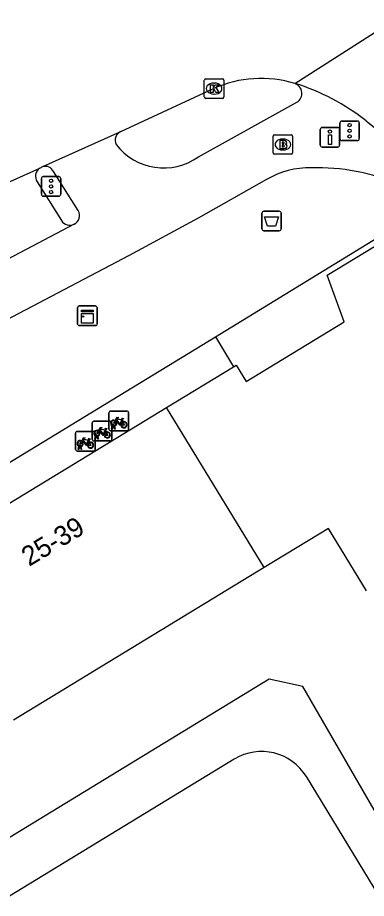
# Model space of a CAD drawing. Extents: x 159888 to 160757, y 384031 to 384746.
# Drawn here: x 160248.39 to 160266.23, y 384650.52 to 384695.58 of the extents above; entities that cross this region are included whole.
import ezdxf

# ---------------------------------------------------------------- set-up
doc = ezdxf.new("R2010")
doc.units = 0
for name, color, linetype in [('IMGEO_Afvalbak', 7, 'Continuous'), ('IMGEO_Brandkraan', 7, 'Continuous'), ('IMGEO_Drukknoppaal', 7, 'Continuous'), ('IMGEO_Fietsenrek', 7, 'Continuous'), ('IMGEO_Fietspad_open', 7, 'Continuous'), ('IMGEO_Kast', 7, 'Continuous'), ('IMGEO_Kolk', 7, 'Continuous'), ('IMGEO_Pand', 7, 'Continuous'), ('IMGEO_Pand_nummerreeks', 7, 'Continuous'), ('IMGEO_Rijbaan_lokaal_gesloten', 7, 'Continuous'), ('IMGEO_Rijbaan_regionaal_gesloten', 7, 'Continuous'), ('IMGEO_Verkeersregelinstallatiepaal', 7, 'Continuous'), ('IMGEO_Voetpad_gesloten', 7, 'Continuous'), ('IMGEO_Voetpad_open', 7, 'Continuous')]:
    doc.layers.add(name, color=color, linetype=linetype)

msp = doc.modelspace()

# ---------------------------------------------------------------- linework, layer by layer
at = {"layer": 'IMGEO_Afvalbak'}
for p, q in [((160260.984, 384685.673), (160261.774, 384685.673)), ((160261.774, 384685.673), (160260.984, 384685.673)), ((160260.884, 384684.773), (160260.884, 384685.573)), ((160260.884, 384685.573), (160260.884, 384684.773)), ((160261.874, 384685.573), (160261.874, 384684.773)), ((160261.874, 384684.773), (160261.874, 384685.573)), ((160261.774, 384684.673), (160260.984, 384684.673)), ((160260.984, 384684.673), (160261.774, 384684.673))]:
    msp.add_line(p, q, dxfattribs=at)
msp.add_lwpolyline([(160261.027, 384685.387), (160261.731, 384685.387), (160261.582, 384684.917), (160261.176, 384684.917), (160261.027, 384685.387)], dxfattribs=at)
for centre, start, end in [((160260.984, 384685.573), 90, 180), ((160260.984, 384685.573), 90, 180), ((160261.774, 384685.573), 0, 90), ((160261.774, 384685.573), 360, 90), ((160260.984, 384684.773), 180, 270), ((160260.984, 384684.773), 180, 270), ((160261.774, 384684.773), 270, 0), ((160261.774, 384684.773), 270, 0)]:
    msp.add_arc(centre, 0.1, start, end, dxfattribs=at)
at = {"layer": 'IMGEO_Brandkraan'}
for p, q in [((160261.457, 384688.661), (160261.457, 384689.513)), ((160261.532, 384689.587), (160262.384, 384689.587)), ((160261.945, 384689.367), (160261.97, 384689.367)), ((160262.458, 384689.513), (160262.458, 384688.661)), ((160261.968, 384688.807), (160261.943, 384688.807)), ((160262.384, 384688.587), (160261.532, 384688.587))]:
    msp.add_line(p, q, dxfattribs=at)
for points in [[(160261.457, 384688.661), (160261.457, 384689.513)], [(160261.532, 384689.587), (160262.384, 384689.587)], [(160261.805, 384689.287), (160261.805, 384688.887), (160262.018, 384688.887)], [(160262.036, 384689.287), (160261.805, 384689.287)], [(160262.458, 384689.513), (160262.458, 384688.661)], [(160261.984, 384689.206), (160261.93, 384689.206), (160261.93, 384689.13)], [(160261.93, 384689.13), (160261.983, 384689.13)], [(160261.992, 384689.054), (160261.93, 384689.054), (160261.93, 384688.973)], [(160261.93, 384688.973), (160261.992, 384688.973)], [(160262.384, 384688.587), (160261.532, 384688.587)]]:
    msp.add_lwpolyline(points, dxfattribs=at)
for centre, radius, start, end in [((160261.534, 384689.511), 0.0765, 91.552, 178.448), ((160261.534, 384689.511), 0.0765, 91.552, 178.448), ((160262.04, 384689.142), 0.145, 59.4692, 91.5367), ((160262.065, 384689.189), 0.0922, 285.5137, 58.1501), ((160262.382, 384689.511), 0.0765, 1.552, 88.448), ((160262.382, 384689.511), 0.0765, 1.552, 88.448), ((160261.985, 384689.168), 0.0379, 267.8285, 90.9355), ((160261.993, 384689.013), 0.0404, 269.8759, 90.5077), ((160262.024, 384689.138), 0.251, 268.6676, 293.5347), ((160262.07, 384688.997), 0.105, 301.3115, 78.989), ((160261.534, 384688.663), 0.0765, 181.552, 268.448), ((160261.534, 384688.663), 0.0765, 181.552, 268.448), ((160262.382, 384688.663), 0.0765, 271.552, 358.448), ((160262.382, 384688.663), 0.0765, 271.552, 358.448)]:
    msp.add_arc(centre, radius, start, end, dxfattribs=at)
for centre, major_axis, ratio, start_param, end_param in [((160261.944, 384689.087), (-0.387, 0.002), 0.722429, 4.712389, 7.853982), ((160261.969, 384689.087), (-0.39, 0.002), 0.717154, 1.570796, 4.712389)]:
    msp.add_ellipse(centre, major_axis=major_axis, ratio=ratio, start_param=start_param, end_param=end_param, dxfattribs=at)
at = {"layer": 'IMGEO_Drukknoppaal'}
for p, q in [((160263.872, 384689.059), (160263.872, 384689.859)), ((160263.872, 384689.859), (160263.872, 384689.059)), ((160263.972, 384689.959), (160264.762, 384689.959)), ((160264.762, 384689.959), (160263.972, 384689.959)), ((160264.862, 384689.859), (160264.862, 384689.059)), ((160264.862, 384689.059), (160264.862, 384689.859)), ((160264.762, 384688.959), (160263.972, 384688.959)), ((160263.972, 384688.959), (160264.762, 384688.959))]:
    msp.add_line(p, q, dxfattribs=at)
msp.add_lwpolyline([(160264.442, 384689.584), (160264.442, 384689.084), (160264.292, 384689.084), (160264.292, 384689.584), (160264.442, 384689.584)], dxfattribs=at)
msp.add_circle((160264.367, 384689.749), 0.085, dxfattribs=at)
for centre, start, end in [((160263.972, 384689.859), 90, 180), ((160263.972, 384689.859), 90, 180), ((160264.762, 384689.859), 0, 90), ((160264.762, 384689.859), 360, 90), ((160263.972, 384689.059), 180, 270), ((160263.972, 384689.059), 180, 270), ((160264.762, 384689.059), 270, 0), ((160264.762, 384689.059), 270, 0)]:
    msp.add_arc(centre, 0.1, start, end, dxfattribs=at)
at = {"layer": 'IMGEO_Fietsenrek'}
for p, q in [((160253.066, 384674.521), (160253.066, 384675.362)), ((160253.066, 384675.362), (160253.066, 384674.521)), ((160253.141, 384675.446), (160253.982, 384675.446)), ((160253.982, 384675.446), (160253.141, 384675.446)), ((160254.066, 384675.371), (160254.066, 384674.53)), ((160254.066, 384674.53), (160254.066, 384675.371)), ((160252.212, 384674), (160252.212, 384674.841)), ((160252.212, 384674.841), (160252.212, 384674)), ((160252.287, 384674.925), (160253.128, 384674.925)), ((160253.128, 384674.925), (160252.287, 384674.925)), ((160253.212, 384674.85), (160253.212, 384674.009)), ((160253.212, 384674.009), (160253.212, 384674.85)), ((160253.753, 384674.995), (160253.789, 384674.9)), ((160251.432, 384674.404), (160252.273, 384674.404)), ((160252.273, 384674.404), (160251.432, 384674.404)), ((160252.899, 384674.474), (160252.935, 384674.379)), ((160253.991, 384674.446), (160253.15, 384674.446)), ((160253.15, 384674.446), (160253.991, 384674.446)), ((160253.193, 384674.53), (160253.232, 384674.69)), ((160253.227, 384674.53), (160253.193, 384674.53)), ((160253.262, 384674.678), (160253.227, 384674.53)), ((160253.304, 384674.702), (160253.303, 384674.706)), ((160253.345, 384674.53), (160253.311, 384674.672)), ((160253.335, 384674.713), (160253.336, 384674.706)), ((160253.343, 384674.676), (160253.378, 384674.53)), ((160253.378, 384674.53), (160253.345, 384674.53)), ((160251.357, 384673.479), (160251.357, 384674.32)), ((160251.357, 384674.32), (160251.357, 384673.479)), ((160252.044, 384673.953), (160252.08, 384673.858)), ((160253.137, 384673.925), (160252.296, 384673.925)), ((160252.296, 384673.925), (160253.137, 384673.925)), ((160252.339, 384674.009), (160252.378, 384674.169)), ((160252.373, 384674.009), (160252.339, 384674.009)), ((160252.357, 384674.329), (160252.357, 384673.488)), ((160252.357, 384673.488), (160252.357, 384674.329)), ((160252.408, 384674.157), (160252.373, 384674.009)), ((160252.45, 384674.181), (160252.449, 384674.185)), ((160252.491, 384674.009), (160252.457, 384674.151)), ((160252.481, 384674.192), (160252.482, 384674.185)), ((160252.489, 384674.155), (160252.524, 384674.009)), ((160252.524, 384674.009), (160252.491, 384674.009)), ((160251.484, 384673.488), (160251.523, 384673.648)), ((160251.518, 384673.488), (160251.484, 384673.488)), ((160251.553, 384673.636), (160251.518, 384673.488)), ((160251.595, 384673.66), (160251.594, 384673.664)), ((160251.636, 384673.488), (160251.602, 384673.63)), ((160251.626, 384673.671), (160251.627, 384673.664)), ((160251.634, 384673.634), (160251.669, 384673.488)), ((160251.669, 384673.488), (160251.636, 384673.488)), ((160252.282, 384673.404), (160251.441, 384673.404)), ((160251.441, 384673.404), (160252.282, 384673.404))]:
    msp.add_line(p, q, dxfattribs=at)
for points in [[(160253.4, 384674.92), (160253.348, 384674.83), (160253.308, 384674.805), (160253.309, 384674.852), (160253.364, 384674.946)], [(160253.379, 384674.972), (160253.474, 384675.136), (160253.56, 384675.122), (160253.562, 384675.113), (160253.506, 384675.102), (160253.479, 384675.057), (160253.735, 384675.016)], [(160253.675, 384674.728), (160253.625, 384674.728), (160253.434, 384674.979), (160253.415, 384674.947)], [(160253.722, 384674.991), (160253.465, 384675.032), (160253.448, 384675.003), (160253.615, 384674.783), (160253.722, 384674.991)], [(160253.77, 384674.893), (160253.74, 384674.97), (160253.631, 384674.752), (160253.674, 384674.752)], [(160253.704, 384674.752), (160253.824, 384674.751), (160253.78, 384674.865)], [(160253.8, 384674.872), (160253.855, 384674.727), (160253.705, 384674.727)], [(160253.735, 384675.016), (160253.76, 384675.065), (160253.754, 384675.069), (160253.731, 384675.073), (160253.719, 384675.08), (160253.718, 384675.083), (160253.72, 384675.088), (160253.815, 384675.073), (160253.817, 384675.063), (160253.807, 384675.05), (160253.795, 384675.044), (160253.781, 384675.05), (160253.753, 384674.995)], [(160252.546, 384674.399), (160252.494, 384674.309), (160252.454, 384674.284), (160252.455, 384674.331), (160252.51, 384674.425)], [(160252.525, 384674.451), (160252.62, 384674.615), (160252.706, 384674.601), (160252.708, 384674.592), (160252.652, 384674.581), (160252.625, 384674.536), (160252.881, 384674.495)], [(160252.821, 384674.207), (160252.771, 384674.207), (160252.58, 384674.458), (160252.561, 384674.426)], [(160252.868, 384674.47), (160252.611, 384674.511), (160252.594, 384674.482), (160252.761, 384674.262), (160252.868, 384674.47)], [(160252.916, 384674.372), (160252.886, 384674.449), (160252.777, 384674.231), (160252.82, 384674.231)], [(160252.881, 384674.495), (160252.906, 384674.544), (160252.9, 384674.548), (160252.877, 384674.552), (160252.865, 384674.559), (160252.864, 384674.562), (160252.866, 384674.567), (160252.961, 384674.552), (160252.963, 384674.542), (160252.953, 384674.529), (160252.941, 384674.523), (160252.927, 384674.529), (160252.899, 384674.474)], [(160251.67, 384673.93), (160251.765, 384674.094), (160251.851, 384674.08), (160251.853, 384674.071), (160251.797, 384674.06), (160251.77, 384674.015), (160252.026, 384673.974)], [(160251.966, 384673.686), (160251.916, 384673.686), (160251.725, 384673.937), (160251.706, 384673.905)], [(160252.013, 384673.949), (160251.756, 384673.99), (160251.739, 384673.961), (160251.906, 384673.741), (160252.013, 384673.949)], [(160252.061, 384673.851), (160252.031, 384673.928), (160251.922, 384673.71), (160251.965, 384673.71)], [(160252.026, 384673.974), (160252.051, 384674.023), (160252.045, 384674.027), (160252.022, 384674.031), (160252.01, 384674.038), (160252.009, 384674.041), (160252.011, 384674.046), (160252.106, 384674.031), (160252.108, 384674.021), (160252.098, 384674.008), (160252.086, 384674.002), (160252.072, 384674.008), (160252.044, 384673.953)], [(160252.85, 384674.231), (160252.97, 384674.23), (160252.926, 384674.344)], [(160252.946, 384674.351), (160253.001, 384674.206), (160252.851, 384674.206)], [(160251.691, 384673.878), (160251.639, 384673.788), (160251.599, 384673.763), (160251.6, 384673.81), (160251.655, 384673.904)], [(160251.995, 384673.71), (160252.115, 384673.709), (160252.071, 384673.823)], [(160252.091, 384673.83), (160252.146, 384673.685), (160251.996, 384673.685)]]:
    msp.add_lwpolyline(points, dxfattribs=at)
for centre, radius, start, end in [((160253.144, 384675.368), 0.0779, 92.4484, 184.2845), ((160253.144, 384675.368), 0.0779, 92.4484, 184.2845), ((160253.988, 384675.368), 0.0779, 2.4484, 94.2845), ((160253.988, 384675.368), 0.0779, 2.4484, 94.2845), ((160252.29, 384674.847), 0.0779, 92.4484, 184.2845), ((160252.29, 384674.847), 0.0779, 92.4484, 184.2845), ((160253.134, 384674.847), 0.0779, 2.4484, 94.2845), ((160253.134, 384674.847), 0.0779, 2.4484, 94.2845), ((160253.306, 384674.831), 0.159, 62.6766, 242.1369), ((160253.306, 384674.831), 0.129, 63.3192, 238.903), ((160253.306, 384674.831), 0.129, 283.6043, 43.4302), ((160253.306, 384674.831), 0.159, 283.5766, 46.6042), ((160253.833, 384674.747), 0.159, 113.3408, 178.3217), ((160253.833, 384674.747), 0.159, 187.0065, 105.7708), ((160253.833, 384674.747), 0.129, 113.923, 177.9556), ((160253.833, 384674.747), 0.129, 188.6715, 104.5883), ((160251.435, 384674.326), 0.0779, 92.4484, 184.2845), ((160251.435, 384674.326), 0.0779, 92.4484, 184.2845), ((160252.279, 384674.326), 0.0779, 2.4484, 94.2845), ((160252.279, 384674.326), 0.0779, 2.4484, 94.2845), ((160252.452, 384674.31), 0.159, 62.6766, 242.1369), ((160252.452, 384674.31), 0.129, 63.3192, 238.903), ((160252.452, 384674.31), 0.129, 283.6043, 43.4302), ((160252.452, 384674.31), 0.159, 283.5766, 46.6042), ((160252.979, 384674.226), 0.159, 113.3408, 178.3217), ((160252.979, 384674.226), 0.159, 187.0065, 105.7708), ((160253.144, 384674.524), 0.0779, 182.4484, 274.2845), ((160253.144, 384674.524), 0.0779, 182.4484, 274.2845), ((160253.286, 384674.702), 0.0499, 12.8025, 158.6934), ((160253.306, 384674.831), 0.159, 253.9967, 271.7867), ((160253.286, 384674.702), 0.0174, 12.8025, 163.4502), ((160253.306, 384674.831), 0.129, 253.415, 269.0204), ((160253.988, 384674.524), 0.0779, 272.4484, 4.2845), ((160253.988, 384674.524), 0.0779, 272.4484, 4.2845), ((160251.597, 384673.789), 0.159, 62.6766, 242.1369), ((160251.597, 384673.789), 0.129, 63.3192, 238.903), ((160252.29, 384674.003), 0.0779, 182.4484, 274.2845), ((160252.29, 384674.003), 0.0779, 182.4484, 274.2845), ((160252.432, 384674.181), 0.0499, 12.8025, 158.6934), ((160252.452, 384674.31), 0.159, 253.9967, 271.7867), ((160252.432, 384674.181), 0.0174, 12.8025, 163.4502), ((160252.452, 384674.31), 0.129, 253.415, 269.0204), ((160252.979, 384674.226), 0.129, 113.923, 177.9556), ((160252.979, 384674.226), 0.129, 188.6715, 104.5883), ((160253.134, 384674.003), 0.0779, 272.4484, 4.2845), ((160253.134, 384674.003), 0.0779, 272.4484, 4.2845), ((160251.435, 384673.482), 0.0779, 182.4484, 274.2845), ((160251.435, 384673.482), 0.0779, 182.4484, 274.2845), ((160251.577, 384673.66), 0.0499, 12.8025, 158.6934), ((160251.597, 384673.789), 0.159, 253.9967, 271.7867), ((160251.577, 384673.66), 0.0174, 12.8025, 163.4502), ((160251.597, 384673.789), 0.129, 253.415, 269.0204), ((160251.597, 384673.789), 0.129, 283.6043, 43.4302), ((160251.597, 384673.789), 0.159, 283.5766, 46.6042), ((160252.124, 384673.705), 0.159, 113.3408, 178.3217), ((160252.124, 384673.705), 0.159, 187.0065, 105.7708), ((160252.124, 384673.705), 0.129, 113.923, 177.9556), ((160252.124, 384673.705), 0.129, 188.6715, 104.5883), ((160252.279, 384673.482), 0.0779, 272.4484, 4.2845), ((160252.279, 384673.482), 0.0779, 272.4484, 4.2845)]:
    msp.add_arc(centre, radius, start, end, dxfattribs=at)
at = {"layer": 'IMGEO_Fietspad_open'}
for points in [[(160257.644, 384688.461), (160262.672, 384691.247)], [(160251.497, 384685.709), (160250.227, 384687.713)], [(160261.124, 384687.295), (160257.631, 384685.322), (160254.104, 384683.407), (160243.453, 384677.816), (160234.319, 384673.277)], [(160251.28, 384685.007), (160246.943, 384682.725)]]:
    msp.add_lwpolyline(points, dxfattribs=at)
for centre, radius, start, end in [((160262.401, 384691.706), 0.533, 300.5782, 71.3841), ((160253.884, 384689.3), 0.5, 114.6774, 204.3436), ((160255.862, 384690.947), 3.059, 217.2863, 305.6363), ((160249.801, 384687.489), 0.481, 27.7801, 103.348), ((160263.277, 384683.719), 4.174, 88.0959, 121.0563), ((160263.758, 384677.463), 10.433, 66.5927, 91.8798), ((160251.064, 384685.458), 0.501, 295.6158, 30.0297)]:
    msp.add_arc(centre, radius, start, end, dxfattribs=at)
at = {"layer": 'IMGEO_Kast'}
for p, q in [((160251.461, 384679.901), (160251.461, 384680.742)), ((160251.461, 384680.742), (160251.461, 384679.901)), ((160251.536, 384680.826), (160252.377, 384680.826)), ((160252.377, 384680.826), (160251.536, 384680.826)), ((160252.461, 384680.751), (160252.461, 384679.91)), ((160252.461, 384679.91), (160252.461, 384680.751)), ((160252.386, 384679.826), (160251.545, 384679.826)), ((160251.545, 384679.826), (160252.386, 384679.826))]:
    msp.add_line(p, q, dxfattribs=at)
for points in [[(160251.656, 384680.616), (160252.256, 384680.616), (160252.256, 384680.531), (160251.656, 384680.531), (160251.656, 384680.616)], [(160251.656, 384680.441), (160252.256, 384680.441), (160252.256, 384679.952), (160251.656, 384679.952), (160251.656, 384680.441)]]:
    msp.add_lwpolyline(points, dxfattribs=at)
msp.add_circle((160251.74, 384680.29), 0.0377, dxfattribs=at)
for centre, start, end in [((160251.539, 384680.748), 92.4484, 184.2845), ((160251.539, 384680.748), 92.4484, 184.2845), ((160252.383, 384680.748), 2.4484, 94.2845), ((160252.383, 384680.748), 2.4484, 94.2845), ((160251.539, 384679.904), 182.4484, 274.2845), ((160251.539, 384679.904), 182.4484, 274.2845), ((160252.383, 384679.904), 272.4484, 4.2845), ((160252.383, 384679.904), 272.4484, 4.2845)]:
    msp.add_arc(centre, 0.0779, start, end, dxfattribs=at)
at = {"layer": 'IMGEO_Kolk'}
for p, q in [((160258.017, 384692.448), (160258.869, 384692.448)), ((160257.942, 384691.522), (160257.942, 384692.374)), ((160258.43, 384692.228), (160258.455, 384692.228)), ((160258.943, 384692.374), (160258.943, 384691.522)), ((160258.453, 384691.668), (160258.428, 384691.668)), ((160258.869, 384691.448), (160258.017, 384691.448))]:
    msp.add_line(p, q, dxfattribs=at)
for points in [[(160258.017, 384692.448), (160258.869, 384692.448)], [(160257.942, 384691.522), (160257.942, 384692.374)], [(160258.263, 384692.148), (160258.386, 384692.148), (160258.386, 384691.997), (160258.516, 384692.148), (160258.68, 384692.148), (160258.534, 384691.997), (160258.687, 384691.748), (160258.535, 384691.748), (160258.45, 384691.912), (160258.386, 384691.845), (160258.386, 384691.748), (160258.263, 384691.748), (160258.263, 384692.148)], [(160258.943, 384692.374), (160258.943, 384691.522)], [(160258.869, 384691.448), (160258.017, 384691.448)]]:
    msp.add_lwpolyline(points, dxfattribs=at)
for centre, start, end in [((160258.019, 384692.372), 91.552, 178.448), ((160258.019, 384692.372), 91.552, 178.448), ((160258.867, 384692.372), 1.552, 88.448), ((160258.867, 384692.372), 1.552, 88.448), ((160258.019, 384691.524), 181.552, 268.448), ((160258.019, 384691.524), 181.552, 268.448), ((160258.867, 384691.524), 271.552, 358.448), ((160258.867, 384691.524), 271.552, 358.448)]:
    msp.add_arc(centre, 0.0765, start, end, dxfattribs=at)
for centre, major_axis, ratio, start_param, end_param in [((160258.429, 384691.948), (-0.387, 0.002), 0.722429, 4.712389, 7.853982), ((160258.454, 384691.948), (-0.39, 0.002), 0.717154, 1.570796, 4.712389)]:
    msp.add_ellipse(centre, major_axis=major_axis, ratio=ratio, start_param=start_param, end_param=end_param, dxfattribs=at)
at = {"layer": 'IMGEO_Pand'}
for points in [[(160259.438, 384677.719), (160259.575, 384677.802), (160260.082, 384676.969), (160265.09, 384680.017), (160264.228, 384682.398), (160266.608, 384683.846), (160274.323, 384671.167)], [(160256.015, 384675.636), (160259.438, 384677.719)], [(160243.201, 384667.839), (160256.015, 384675.636)], [(160261, 384667.439), (160256.015, 384675.636)], [(160266.243, 384666.252), (160264.299, 384669.446), (160261, 384667.439)], [(160261, 384667.439), (160248.186, 384659.641)]]:
    msp.add_lwpolyline(points, dxfattribs=at)
at = {"layer": 'IMGEO_Rijbaan_lokaal_gesloten'}
msp.add_lwpolyline([(160266.214, 384690.293), (160269.451, 384687.696)], dxfattribs=at)
msp.add_arc((160259.263, 384681.509), 11.202, 51.6444, 72.823, dxfattribs=at)
at = {"layer": 'IMGEO_Rijbaan_regionaal_gesloten'}
for points in [[(160262.571, 384692.211), (160267.856, 384695.579)], [(160253.675, 384689.755), (160258.417, 384691.954)], [(160249.69, 384687.957), (160253.675, 384689.755)], [(160245.149, 384685.907), (160249.524, 384687.881)], [(160249.524, 384687.881), (160249.69, 384687.957)]]:
    msp.add_lwpolyline(points, dxfattribs=at)
msp.add_arc((160260.841, 384686.478), 5.988, 73.2052, 113.8754, dxfattribs=at)
at = {"layer": 'IMGEO_Verkeersregelinstallatiepaal'}
for p, q in [((160264.874, 384689.388), (160264.874, 384690.188)), ((160264.874, 384690.188), (160264.874, 384689.388)), ((160264.974, 384690.288), (160265.764, 384690.288)), ((160265.764, 384690.288), (160264.974, 384690.288)), ((160265.864, 384690.188), (160265.864, 384689.388)), ((160265.864, 384689.388), (160265.864, 384690.188)), ((160265.764, 384689.288), (160264.974, 384689.288)), ((160264.974, 384689.288), (160265.764, 384689.288)), ((160249.708, 384687.444), (160250.498, 384687.444)), ((160250.498, 384687.444), (160249.708, 384687.444)), ((160249.608, 384686.544), (160249.608, 384687.344)), ((160249.608, 384687.344), (160249.608, 384686.544)), ((160250.598, 384687.344), (160250.598, 384686.544)), ((160250.598, 384686.544), (160250.598, 384687.344)), ((160250.498, 384686.444), (160249.708, 384686.444)), ((160249.708, 384686.444), (160250.498, 384686.444))]:
    msp.add_line(p, q, dxfattribs=at)
for centre in [(160265.369, 384690.078), (160265.369, 384689.788), (160265.369, 384689.498), (160250.103, 384687.234), (160250.103, 384686.944), (160250.103, 384686.654)]:
    msp.add_circle(centre, 0.085, dxfattribs=at)
for centre, start, end in [((160264.974, 384690.188), 90, 180), ((160264.974, 384690.188), 90, 180), ((160265.764, 384690.188), 0, 90), ((160265.764, 384690.188), 360, 90), ((160264.974, 384689.388), 180, 270), ((160264.974, 384689.388), 180, 270), ((160265.764, 384689.388), 270, 0), ((160265.764, 384689.388), 270, 0), ((160249.708, 384687.344), 90, 180), ((160249.708, 384687.344), 90, 180), ((160250.498, 384687.344), 0, 90), ((160250.498, 384687.344), 360, 90), ((160249.708, 384686.544), 180, 270), ((160249.708, 384686.544), 180, 270), ((160250.498, 384686.544), 270, 0), ((160250.498, 384686.544), 270, 0)]:
    msp.add_arc(centre, 0.1, start, end, dxfattribs=at)
at = {"layer": 'IMGEO_Voetpad_gesloten'}
for points in [[(160273.725, 384600.111), (160290.976, 384610.866), (160291.528, 384611.183), (160292.129, 384613.093), (160281.338, 384630.928), (160267.258, 384653.953), (160262.987, 384661.364), (160261.252, 384661.738), (160209.474, 384630.138)], [(160259.476, 384657.646), (160243.075, 384647.641)], [(160288.027, 384615.837), (160263.16, 384656.744)]]:
    msp.add_lwpolyline(points, dxfattribs=at)
msp.add_arc((160260.864, 384655.343), 2.689, 31.4016, 121.0828, dxfattribs=at)
at = {"layer": 'IMGEO_Voetpad_open'}
for points in [[(160249.397, 384687.176), (160250.641, 384685.196)], [(160258.508, 384679.247), (160267.612, 384684.826)], [(160201.065, 384644.22), (160258.508, 384679.247)], [(160258.508, 384679.247), (160259.438, 384677.719)]]:
    msp.add_lwpolyline(points, dxfattribs=at)
for centre, radius, start, end in [((160249.822, 384687.463), 0.513, 125.5035, 214.0728), ((160251.066, 384685.457), 0.498, 211.5455, 295.5007)]:
    msp.add_arc(centre, radius, start, end, dxfattribs=at)

# ---------------------------------------------------------------- texts
at = {"layer": 'IMGEO_Pand_nummerreeks'}
msp.add_text('25-39', height=1, rotation=31.1337, dxfattribs=at).set_placement((160248.982, 384667.475))

doc.saveas('drawing.dxf')
